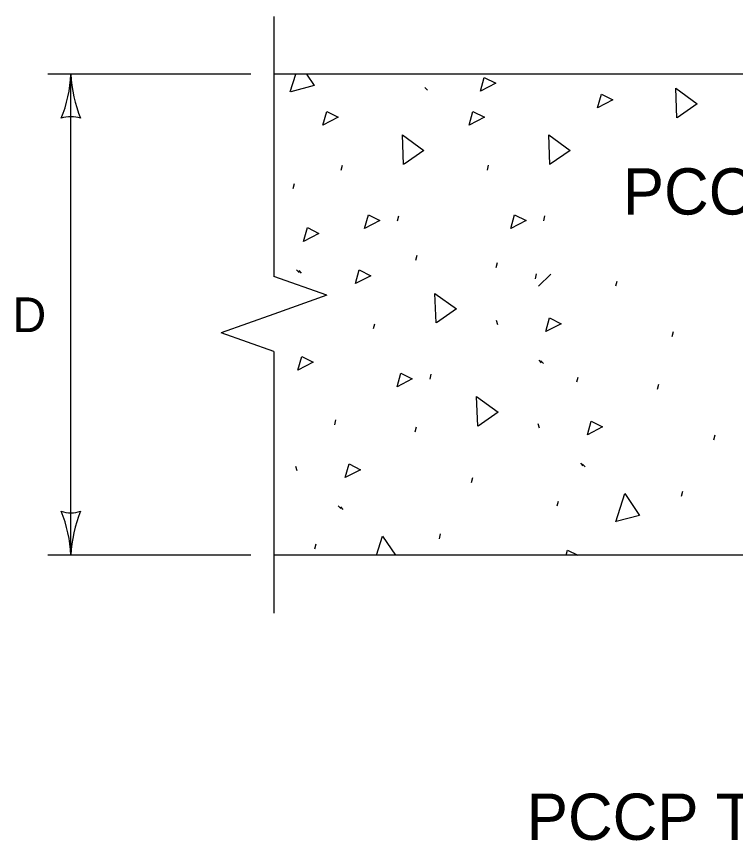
# Model space of a CAD drawing. Extents: x 49979.1 to 50021, y 49966.7 to 50011.4.
# Drawn here: x 50007.769 to 50009.012, y 49991.174 to 49992.599 of the extents above; entities that cross this region are included whole.
import ezdxf

# ---------------------------------------------------------------- set-up
doc = ezdxf.new("R2010")
doc.units = 0
for name, color, linetype in [('Level 1', 7, 'Continuous'), ('Level 13', 7, 'Continuous'), ('Level 2', 7, 'Continuous'), ('Level 3', 7, 'Continuous'), ('Level 6', 7, 'Continuous')]:
    doc.layers.add(name, color=color, linetype=linetype)

msp = doc.modelspace()

# ---------------------------------------------------------------- linework, layer by layer
at = {"layer": 'Level 1'}
for p, q in [((50009.7246, 49992.4991), (50008.214, 49992.4991)), ((50008.6716, 49992.1329), (50008.6926, 49992.1538)), ((50009.7246, 49991.6675), (50008.214, 49991.6675))]:
    msp.add_line(p, q, dxfattribs=at)
at = {"layer": 'Level 13'}
for p, q in [((50008.4752, 49992.4763), (50008.4796, 49992.4717)), ((50008.3303, 49992.3334), (50008.3324, 49992.3419)), ((50008.5831, 49992.3334), (50008.5852, 49992.3419)), ((50008.2472, 49992.3018), (50008.2493, 49992.3103)), ((50008.4277, 49992.246), (50008.4298, 49992.2545)), ((50008.6806, 49992.246), (50008.6827, 49992.2545)), ((50008.4594, 49992.1777), (50008.4615, 49992.1862)), ((50008.253, 49992.1612), (50008.2574, 49992.1566)), ((50008.2569, 49992.1599), (50008.2613, 49992.1552)), ((50008.5986, 49992.1653), (50008.6007, 49992.1738)), ((50008.6661, 49992.1457), (50008.6682, 49992.1542)), ((50008.8053, 49992.1332), (50008.8074, 49992.1417)), ((50008.3864, 49992.0594), (50008.3885, 49992.0679)), ((50008.5982, 49992.0741), (50008.6005, 49992.0664)), ((50008.9028, 49992.0458), (50008.9049, 49992.0543)), ((50008.6719, 49992.0051), (50008.6763, 49992.0005)), ((50008.6758, 49992.0038), (50008.6802, 49991.9991)), ((50008.4839, 49991.972), (50008.486, 49991.9805)), ((50008.7381, 49991.9671), (50008.7402, 49991.9756)), ((50008.8774, 49991.9547), (50008.8795, 49991.9632)), ((50008.3192, 49991.8933), (50008.3213, 49991.9017)), ((50008.4585, 49991.8808), (50008.4606, 49991.8893)), ((50008.6702, 49991.8955), (50008.6725, 49991.8878)), ((50008.9748, 49991.8673), (50008.9769, 49991.8758)), ((50008.2513, 49991.8217), (50008.2536, 49991.814)), ((50008.744, 49991.8266), (50008.7484, 49991.822)), ((50008.7478, 49991.8252), (50008.7522, 49991.8206)), ((50008.5559, 49991.7934), (50008.558, 49991.8019)), ((50008.919, 49991.7699), (50008.9211, 49991.7784)), ((50008.7038, 49991.7527), (50008.7059, 49991.7611)), ((50008.325, 49991.7527), (50008.3295, 49991.7481)), ((50008.3289, 49991.7513), (50008.3333, 49991.7467)), ((50008.5001, 49991.696), (50008.5022, 49991.7045)), ((50008.2849, 49991.6788), (50008.287, 49991.6873))]:
    msp.add_line(p, q, dxfattribs=at)
for points in [[(50008.2421, 49992.4686), (50008.2519, 49992.4991)], [(50008.2702, 49992.4991), (50008.2835, 49992.4795), (50008.243, 49992.4688)], [(50008.571, 49992.4698), (50008.5777, 49992.4935), (50008.5975, 49992.4835), (50008.571, 49992.4698)], [(50008.9107, 49992.4237), (50008.9088, 49992.4749), (50008.9458, 49992.4481), (50008.9114, 49992.4241)], [(50008.7738, 49992.4411), (50008.7804, 49992.4648), (50008.8002, 49992.4548), (50008.7738, 49992.4411)], [(50008.2987, 49992.4112), (50008.3053, 49992.435), (50008.3251, 49992.4249), (50008.2987, 49992.4112)], [(50008.5515, 49992.4112), (50008.5581, 49992.435), (50008.578, 49992.4249), (50008.5515, 49992.4112)], [(50008.4383, 49992.3431), (50008.4364, 49992.3943), (50008.4734, 49992.3675), (50008.439, 49992.3435)], [(50008.6911, 49992.3431), (50008.6892, 49992.3943), (50008.7262, 49992.3675), (50008.6919, 49992.3435)], [(50008.3707, 49992.2327), (50008.3774, 49992.2564), (50008.3972, 49992.2464), (50008.3707, 49992.2327)], [(50008.6235, 49992.2327), (50008.6302, 49992.2564), (50008.65, 49992.2464), (50008.6235, 49992.2327)], [(50008.2651, 49992.2103), (50008.2718, 49992.234), (50008.2916, 49992.2239), (50008.2651, 49992.2103)], [(50008.3548, 49992.1372), (50008.3615, 49992.161), (50008.3813, 49992.1509), (50008.3548, 49992.1372)], [(50008.4944, 49992.0691), (50008.4925, 49992.1203), (50008.5296, 49992.0935), (50008.4952, 49992.0695)], [(50008.684, 49992.0542), (50008.6907, 49992.0779), (50008.7105, 49992.0678), (50008.684, 49992.0542)], [(50008.2554, 49991.9874), (50008.2621, 49992.0111), (50008.2819, 49992.0011), (50008.2554, 49991.9874)], [(50008.4269, 49991.9587), (50008.4335, 49991.9824), (50008.4533, 49991.9724), (50008.4269, 49991.9587)], [(50008.5664, 49991.8906), (50008.5646, 49991.9418), (50008.6016, 49991.9149), (50008.5672, 49991.891)], [(50008.7561, 49991.8756), (50008.7627, 49991.8993), (50008.7825, 49991.8893), (50008.7561, 49991.8756)], [(50008.3371, 49991.8017), (50008.3438, 49991.8255), (50008.3636, 49991.8154), (50008.3371, 49991.8017)], [(50008.8051, 49991.7254), (50008.8208, 49991.7742), (50008.8464, 49991.7363), (50008.806, 49991.7256)], [(50008.3913, 49991.6675), (50008.4019, 49991.7003), (50008.4241, 49991.6675)], [(50008.7192, 49991.6675), (50008.7217, 49991.6765), (50008.7395, 49991.6675)]]:
    msp.add_lwpolyline(points, dxfattribs=at)
at = {"layer": 'Level 3'}
for p, q in [((50008.174, 49992.4991), (50007.8228, 49992.4991)), ((50007.8628, 49991.6675), (50007.8628, 49992.4991)), ((50008.174, 49991.6675), (50007.8228, 49991.6675))]:
    msp.add_line(p, q, dxfattribs=at)
for centre, radius, start, end in [((50007.6407, 49992.5082), 0.2223, 337.456, 357.6395), ((50008.0955, 49992.5106), 0.233, 182.8273, 202.0772), ((50007.8628, 49992.3709), 0.0548, 72.1388, 107.8612), ((50007.8628, 49991.7957), 0.0548, 252.1388, 287.8612), ((50007.6301, 49991.656), 0.233, 2.8273, 22.0772), ((50008.0849, 49991.6584), 0.2223, 157.456, 177.6395)]:
    msp.add_arc(centre, radius, start, end, dxfattribs=at)
at = {"layer": 'Level 6'}
for p, q in [((50008.214, 49992.5991), (50008.214, 49992.1494)), ((50008.3054, 49992.117), (50008.214, 49992.1494)), ((50008.3054, 49992.117), (50008.214, 49992.0846)), ((50008.214, 49992.0846), (50008.1226, 49992.0522)), ((50008.214, 49992.0198), (50008.1226, 49992.0522)), ((50008.214, 49992.0198), (50008.214, 49991.5675))]:
    msp.add_line(p, q, dxfattribs=at)

# ---------------------------------------------------------------- texts
at = {"layer": 'Level 2'}
for s, p in [('PCCP', (50008.8173, 49992.2566)), ('PCCP TO PMS LONGITUDINAL JOINT', (50008.6512, 49991.1754))]:
    msp.add_text(s, height=0.08, dxfattribs=at).set_placement(p)
msp.add_text('D', height=0.06, rotation=360, dxfattribs=at).set_placement((50007.7621, 49992.0533))

doc.saveas('drawing.dxf')
